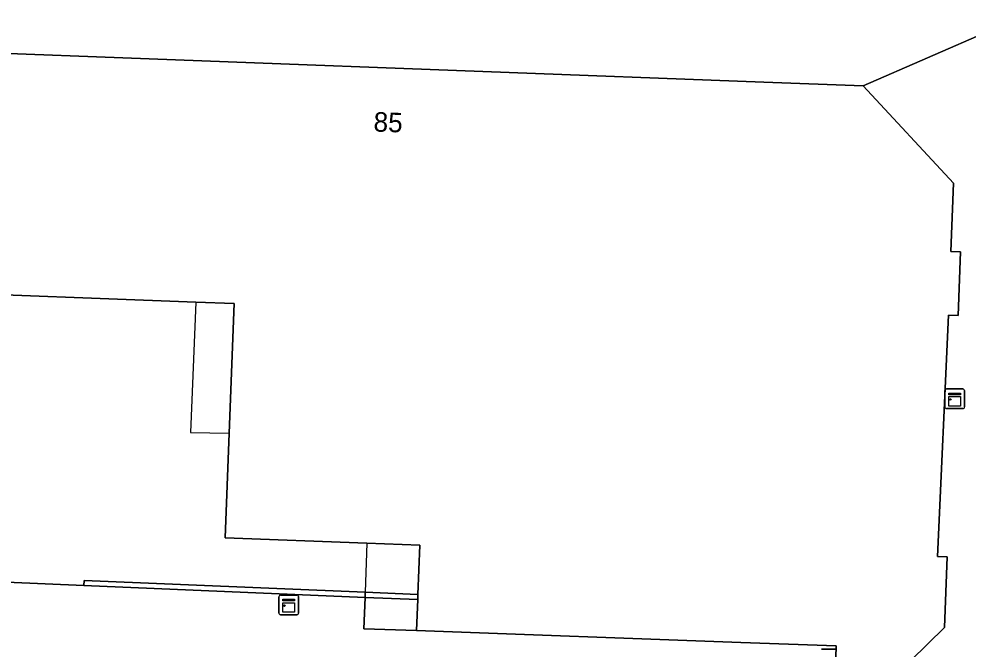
# Model space of a CAD drawing. Extents: x 160888 to 161385, y 386490 to 386908.
# Drawn here: x 161047.88 to 161096.46, y 386839.4 to 386871.64 of the extents above; entities that cross this region are included whole.
import ezdxf

# ---------------------------------------------------------------- set-up
doc = ezdxf.new("R2010")
doc.units = 0
for name, color, linetype in [('IMGEO_Afvalbak', 7, 'Continuous'), ('IMGEO_Erf', 7, 'Continuous'), ('IMGEO_Kast', 7, 'Continuous'), ('IMGEO_Muur', 7, 'Continuous'), ('IMGEO_Pand', 7, 'Continuous'), ('IMGEO_Pand_nummerreeks', 7, 'Continuous'), ('IMGEO_Pand_overbouw', 7, 'Continuous'), ('IMGEO_Voetgangersgebied_open', 7, 'Continuous'), ('IMGEO_Voetpad_open', 7, 'Continuous')]:
    doc.layers.add(name, color=color, linetype=linetype)

msp = doc.modelspace()

# ---------------------------------------------------------------- linework, layer by layer
at = {"layer": 'IMGEO_Afvalbak'}
for p, q in [((161088.96, 386839.396), (161089.75, 386839.396)), ((161089.75, 386839.396), (161088.96, 386839.396))]:
    msp.add_line(p, q, dxfattribs=at)
at = {"layer": 'IMGEO_Erf'}
for points in [[(161058.642, 386850.434), (161058.893, 386857.072), (161056.937, 386857.146), (161042.665, 386857.686), (161042.097, 386843.272), (161047.251, 386843.07), (161047.24, 386842.811), (161051.209, 386842.641), (161051.22, 386842.901), (161065.605, 386842.299), (161068.305, 386842.186), (161068.399, 386844.702), (161065.695, 386844.804), (161058.44, 386845.077)], [(161068.235, 386840.335), (161068.295, 386841.926), (161065.595, 386842.039), (161065.537, 386840.433)]]:
    msp.add_lwpolyline(points, close=True, dxfattribs=at)
at = {"layer": 'IMGEO_Kast'}
for p, q in [((161095.279, 386851.777), (161095.279, 386852.618)), ((161095.279, 386852.618), (161095.279, 386851.777)), ((161095.354, 386852.702), (161096.195, 386852.702)), ((161096.195, 386852.702), (161095.354, 386852.702)), ((161096.279, 386852.627), (161096.279, 386851.786)), ((161096.279, 386851.786), (161096.279, 386852.627)), ((161096.204, 386851.702), (161095.363, 386851.702)), ((161095.363, 386851.702), (161096.204, 386851.702)), ((161061.189, 386841.227), (161061.189, 386842.068)), ((161061.189, 386842.068), (161061.189, 386841.227)), ((161061.264, 386842.152), (161062.105, 386842.152)), ((161062.105, 386842.152), (161061.264, 386842.152)), ((161062.189, 386842.077), (161062.189, 386841.236)), ((161062.189, 386841.236), (161062.189, 386842.077)), ((161062.114, 386841.152), (161061.273, 386841.152)), ((161061.273, 386841.152), (161062.114, 386841.152))]:
    msp.add_line(p, q, dxfattribs=at)
for points in [[(161095.474, 386852.492), (161096.074, 386852.492), (161096.074, 386852.407), (161095.474, 386852.407), (161095.474, 386852.492)], [(161095.474, 386852.317), (161096.074, 386852.317), (161096.074, 386851.828), (161095.474, 386851.828), (161095.474, 386852.317)], [(161061.384, 386841.942), (161061.984, 386841.942), (161061.984, 386841.857), (161061.384, 386841.857), (161061.384, 386841.942)], [(161061.384, 386841.767), (161061.984, 386841.767), (161061.984, 386841.278), (161061.384, 386841.278), (161061.384, 386841.767)]]:
    msp.add_lwpolyline(points, dxfattribs=at)
for centre in [(161095.558, 386852.166), (161061.468, 386841.616)]:
    msp.add_circle(centre, 0.0377, dxfattribs=at)
for centre, start, end in [((161095.357, 386852.624), 92.4484, 184.2845), ((161095.357, 386852.624), 92.4484, 184.2845), ((161096.201, 386852.624), 2.4484, 94.2845), ((161096.201, 386852.624), 2.4484, 94.2845), ((161095.357, 386851.78), 182.4484, 274.2845), ((161095.357, 386851.78), 182.4484, 274.2845), ((161096.201, 386851.78), 272.4484, 4.2845), ((161096.201, 386851.78), 272.4484, 4.2845), ((161061.267, 386842.074), 92.4484, 184.2845), ((161061.267, 386842.074), 92.4484, 184.2845), ((161062.111, 386842.074), 2.4484, 94.2845), ((161062.111, 386842.074), 2.4484, 94.2845), ((161061.267, 386841.23), 182.4484, 274.2845), ((161061.267, 386841.23), 182.4484, 274.2845), ((161062.111, 386841.23), 272.4484, 4.2845), ((161062.111, 386841.23), 272.4484, 4.2845)]:
    msp.add_arc(centre, 0.0779, start, end, dxfattribs=at)
at = {"layer": 'IMGEO_Muur'}
msp.add_lwpolyline([(161065.595, 386842.039), (161065.605, 386842.299), (161051.22, 386842.901), (161051.209, 386842.641)], close=True, dxfattribs=at)
for points in [[(161065.605, 386842.299), (161068.305, 386842.186)], [(161068.295, 386841.926), (161065.595, 386842.039)]]:
    msp.add_lwpolyline(points, dxfattribs=at)
at = {"layer": 'IMGEO_Pand'}
for points in [[(161093.53, 386838.801), (161095.255, 386840.499), (161095.392, 386844.117), (161094.893, 386844.136), (161095.463, 386856.474), (161095.962, 386856.455), (161096.085, 386859.722), (161095.585, 386859.74), (161095.717, 386863.238), (161091.101, 386868.215), (161086.005, 386868.407), (161042.835, 386870.038)], [(161042.665, 386857.686), (161056.937, 386857.146), (161058.893, 386857.072), (161058.642, 386850.434), (161058.44, 386845.077), (161065.695, 386844.804), (161068.399, 386844.702), (161068.305, 386842.186), (161068.295, 386841.926), (161068.235, 386840.335), (161084.829, 386839.735), (161089.715, 386839.558), (161089.69, 386838.959)]]:
    msp.add_lwpolyline(points, dxfattribs=at)
at = {"layer": 'IMGEO_Pand_overbouw'}
for points in [[(161056.937, 386857.146), (161056.656, 386850.47), (161058.642, 386850.434), (161058.893, 386857.072)], [(161065.695, 386844.804), (161065.605, 386842.299), (161065.596, 386842.062), (161065.595, 386842.039), (161065.537, 386840.433), (161068.235, 386840.335), (161068.295, 386841.926), (161068.305, 386842.186), (161068.399, 386844.702)]]:
    msp.add_lwpolyline(points, close=True, dxfattribs=at)
at = {"layer": 'IMGEO_Voetgangersgebied_open'}
for points in [[(161120.067, 386845.369), (161120.551, 386857.609), (161118.549, 386857.687), (161115.257, 386866.814), (161114.398, 386844.72), (161109.327, 386844.907), (161110.225, 386867.01), (161110.434, 386872.136), (161105.986, 386872.318), (161105.088, 386850.158), (161104.881, 386845.062), (161099.861, 386845.272), (161100.069, 386850.343), (161100.979, 386872.509), (161091.101, 386868.215), (161095.717, 386863.238), (161095.585, 386859.74), (161096.085, 386859.722), (161095.962, 386856.455), (161095.463, 386856.474), (161094.893, 386844.136), (161095.392, 386844.117), (161095.255, 386840.499), (161093.53, 386838.801)], [(161089.69, 386838.959), (161089.715, 386839.558), (161084.829, 386839.735), (161068.235, 386840.335), (161065.537, 386840.433), (161065.595, 386842.039), (161051.209, 386842.641), (161047.24, 386842.811)]]:
    msp.add_lwpolyline(points, dxfattribs=at)
at = {"layer": 'IMGEO_Voetpad_open'}
msp.add_lwpolyline([(160988.113, 386879.42), (160988.085, 386877.583), (160973.52, 386878.149), (160973.222, 386870.514), (160982.977, 386870.114), (160983.988, 386870.07), (160998.471, 386869.439), (161000, 386869.372), (161002.18, 386869.277), (161017.574, 386868.605), (161022.345, 386868.321), (161040.517, 386867.696), (161042.835, 386870.038), (161086.005, 386868.407), (161091.101, 386868.215), (161100.979, 386872.509), (161105.986, 386872.318), (161110.434, 386872.136), (161115.457, 386871.94), (161115.257, 386866.814), (161118.549, 386857.687), (161119.79, 386888.855)], dxfattribs=at)
msp.add_lwpolyline([(161068.295, 386841.926), (161068.305, 386842.186), (161065.605, 386842.299), (161065.595, 386842.039)], close=True, dxfattribs=at)

# ---------------------------------------------------------------- texts
at = {"layer": 'IMGEO_Pand_nummerreeks'}
msp.add_text('85', height=1, rotation=357.837, dxfattribs=at).set_placement((161066.019, 386865.881))

doc.saveas('drawing.dxf')
